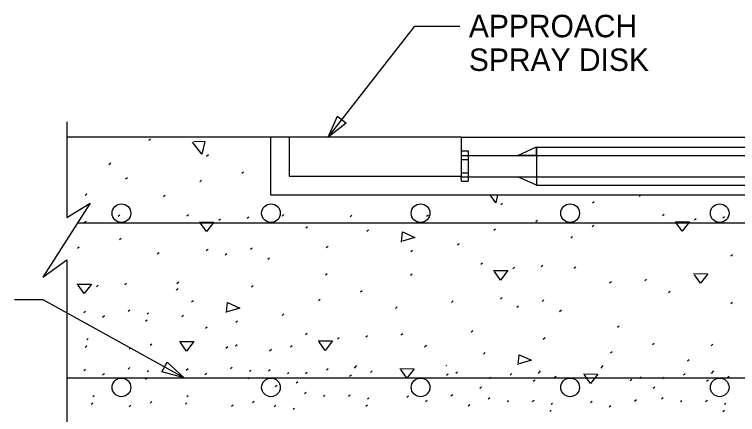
# Model space of a CAD drawing. Extents: x 3239 to 4230, y -4276 to -2494.
# Drawn here: x 3373 to 3469.7, y -3429.6 to -3376.1 of the extents above; entities that cross this region are included whole.
import ezdxf

# ---------------------------------------------------------------- set-up
doc = ezdxf.new("R2010")
doc.units = 0
doc.layers.add('2', color=7, linetype='Continuous')

msp = doc.modelspace()

# ---------------------------------------------------------------- linework, layer by layer
at = {"layer": '2'}
for p, q in [((3380.058, -3390.462), (3380.058, -3403.224)), ((3390.777, -3392.515), (3380.058, -3392.515)), ((3432.777, -3392.515), (3390.777, -3392.515)), ((3391.016, -3392.888), (3391.249, -3392.702)), ((3407.277, -3392.515), (3407.277, -3400.215)), ((3409.777, -3392.515), (3409.777, -3397.715)), ((3432.777, -3392.515), (3432.777, -3397.79)), ((3432.777, -3392.515), (3671.69, -3392.515)), ((3432.819, -3394.34), (3433.719, -3394.34)), ((3433.719, -3394.34), (3433.719, -3398.39)), ((3442.858, -3395.022), (3442.854, -3393.809)), ((3442.858, -3393.818), (3574.241, -3393.818)), ((3442.858, -3393.818), (3442.858, -3398.912)), ((3398.731, -3395.023), (3398.964, -3394.836)), ((3432.777, -3394.94), (3435.277, -3394.94)), ((3432.819, -3395.465), (3433.719, -3395.465)), ((3435.277, -3394.94), (3574.241, -3394.94)), ((3385.67, -3396.131), (3385.903, -3395.945)), ((3403.437, -3397.306), (3403.67, -3397.119)), ((3432.819, -3397.265), (3433.719, -3397.265)), ((3387.904, -3398.067), (3388.137, -3397.881)), ((3397.822, -3398.447), (3398.055, -3398.261)), ((3409.777, -3397.715), (3432.777, -3397.715)), ((3432.777, -3397.79), (3435.277, -3397.79)), ((3432.819, -3398.39), (3432.777, -3397.79)), ((3432.819, -3398.39), (3433.719, -3398.39)), ((3435.277, -3397.79), (3574.241, -3397.79)), ((3442.858, -3398.912), (3574.241, -3398.912)), ((3382.499, -3400.256), (3382.732, -3400.07)), ((3392.953, -3400.428), (3393.186, -3400.241)), ((3407.277, -3400.215), (3579.7, -3400.215)), ((3456.558, -3400.393), (3456.781, -3400.215)), ((3383.178, -3401.33), (3376.812, -3411.2)), ((3380.058, -3403.224), (3383.178, -3401.33)), ((3438.056, -3401.498), (3438.289, -3401.312)), ((3450.315, -3401.279), (3450.548, -3401.092)), ((3386.892, -3403.051), (3387.125, -3402.865)), ((3396.074, -3403.005), (3396.307, -3402.819)), ((3404.136, -3403.317), (3404.369, -3403.13)), ((3408.84, -3403.034), (3409.073, -3402.848)), ((3417.906, -3403.126), (3418.139, -3402.94)), ((3428.154, -3403.059), (3428.387, -3402.873)), ((3459.68, -3402.971), (3459.913, -3402.784)), ((3467.741, -3403.282), (3467.974, -3403.096)), ((3381.498, -3403.936), (3591.059, -3403.936)), ((3382.371, -3403.903), (3382.604, -3403.716)), ((3400.362, -3403.596), (3400.595, -3403.41)), ((3442.762, -3403.781), (3442.995, -3403.595)), ((3450.268, -3404.447), (3450.501, -3404.261)), ((3463.967, -3403.562), (3464.2, -3403.376)), ((3412.008, -3404.619), (3412.241, -3404.432)), ((3420.14, -3405.063), (3420.373, -3404.876)), ((3437.147, -3404.923), (3437.38, -3404.736)), ((3387.077, -3406.186), (3387.31, -3406)), ((3447.422, -3405.971), (3447.655, -3405.785)), ((3381.462, -3407.328), (3381.695, -3407.141)), ((3414.734, -3407.251), (3414.967, -3407.065)), ((3432.278, -3406.903), (3432.511, -3406.717)), ((3392.138, -3408.093), (3392.371, -3407.906)), ((3398.684, -3407.65), (3398.917, -3407.464)), ((3401.189, -3408.234), (3401.422, -3408.048)), ((3404.6, -3407.461), (3404.832, -3407.275)), ((3426.034, -3407.788), (3426.267, -3407.602)), ((3468.812, -3408.359), (3469.045, -3408.173)), ((3376.812, -3411.2), (3380.058, -3408.892)), ((3380.058, -3408.892), (3380.058, -3436.042)), ((3406.926, -3408.798), (3407.159, -3408.612)), ((3435.399, -3409.481), (3435.632, -3409.294)), ((3439.687, -3410.072), (3439.92, -3409.885)), ((3443.461, -3409.792), (3443.694, -3409.606)), ((3447.85, -3410.006), (3448.083, -3409.82)), ((3414.607, -3410.898), (3414.84, -3410.712)), ((3425.987, -3410.957), (3426.22, -3410.771)), ((3387.776, -3412.197), (3388.009, -3412.011)), ((3394.77, -3412.03), (3395.003, -3411.844)), ((3452.624, -3411.959), (3452.857, -3411.772)), ((3457.327, -3411.677), (3457.56, -3411.49)), ((3384.002, -3412.477), (3384.235, -3412.29)), ((3394.677, -3412.916), (3394.91, -3412.729)), ((3404.739, -3412.493), (3404.972, -3412.307)), ((3419.313, -3413.181), (3419.546, -3412.995)), ((3438.009, -3414.126), (3438.242, -3413.939)), ((3460.496, -3413.261), (3460.729, -3413.074)), ((3396.725, -3414.497), (3396.958, -3414.311)), ((3413.698, -3414.323), (3413.931, -3414.137)), ((3431.462, -3414.568), (3431.695, -3414.382)), ((3443.61, -3414.433), (3443.843, -3414.246)), ((3468.812, -3414.728), (3469.045, -3414.541)), ((3382.324, -3415.945), (3382.557, -3415.759)), ((3388.24, -3415.756), (3388.473, -3415.57)), ((3423.972, -3415.371), (3424.205, -3415.185)), ((3440.199, -3415.206), (3440.432, -3415.02)), ((3445.937, -3415.77), (3446.17, -3415.583)), ((3384.829, -3416.53), (3385.062, -3416.343)), ((3390.777, -3416.103), (3390.95, -3415.965)), ((3395.42, -3416.454), (3395.653, -3416.268)), ((3408.829, -3416.303), (3409.062, -3416.117)), ((3390.566, -3417.093), (3390.777, -3416.925)), ((3398.589, -3418.038), (3398.822, -3417.852)), ((3402.619, -3417.223), (3402.852, -3417.037)), ((3453.652, -3417.904), (3453.885, -3417.718)), ((3411.95, -3418.881), (3412.183, -3418.694)), ((3424.715, -3418.91), (3424.948, -3418.724)), ((3434.095, -3418.506), (3434.328, -3418.319)), ((3382.706, -3419.555), (3382.879, -3419.417)), ((3416.237, -3419.472), (3416.47, -3419.285)), ((3420.012, -3419.192), (3420.245, -3419.006)), ((3443.75, -3419.465), (3443.983, -3419.279)), ((3382.495, -3420.546), (3382.706, -3420.377)), ((3388.379, -3420.789), (3388.612, -3420.602)), ((3391.18, -3420.296), (3391.413, -3420.109)), ((3401.314, -3420.671), (3401.547, -3420.485)), ((3402.573, -3420.391), (3402.806, -3420.205)), ((3409.953, -3420.53), (3410.186, -3420.343)), ((3427.884, -3420.494), (3428.117, -3420.308)), ((3458.358, -3420.187), (3458.591, -3420.001)), ((3466.178, -3420.357), (3466.411, -3420.171)), ((3407.152, -3421.023), (3407.385, -3420.836)), ((3435.736, -3421.469), (3435.969, -3421.282)), ((3452.743, -3421.329), (3452.976, -3421.143)), ((3463.017, -3422.377), (3463.25, -3422.191)), ((3382.324, -3423.669), (3382.557, -3423.482)), ((3388.24, -3423.48), (3388.473, -3423.293)), ((3396.009, -3423.61), (3396.242, -3423.424)), ((3401.924, -3423.421), (3402.157, -3423.235)), ((3404.462, -3423.768), (3404.634, -3423.63)), ((3407.012, -3423.714), (3407.245, -3423.527)), ((3414.748, -3423.572), (3414.981, -3423.386)), ((3430.75, -3423.015), (3430.843, -3422.941)), ((3384.829, -3424.253), (3385.062, -3424.067)), ((3390.777, -3423.827), (3390.95, -3423.688)), ((3398.514, -3424.195), (3398.747, -3424.008)), ((3404.251, -3424.758), (3404.462, -3424.59)), ((3409.55, -3424.061), (3409.722, -3423.922)), ((3411.948, -3424.065), (3412.181, -3423.879)), ((3417.855, -3424.416), (3418.088, -3424.23)), ((3420.655, -3423.923), (3420.888, -3423.737)), ((3430.79, -3424.299), (3431.023, -3424.112)), ((3432.048, -3424.019), (3432.281, -3423.833)), ((3436.51, -3424.767), (3436.743, -3424.581)), ((3439.311, -3424.274), (3439.544, -3424.088)), ((3445.218, -3424.625), (3445.451, -3424.439)), ((3456.611, -3424.721), (3456.843, -3424.535)), ((3459.685, -3424.767), (3459.918, -3424.581)), ((3462.485, -3424.274), (3462.718, -3424.088)), ((3468.392, -3424.625), (3468.625, -3424.439)), ((3380.058, -3424.646), (3612.142, -3424.646)), ((3390.566, -3424.817), (3390.777, -3424.648)), ((3410.713, -3425.328), (3410.946, -3425.141)), ((3442.417, -3425.118), (3442.65, -3424.932)), ((3455.352, -3425.001), (3455.585, -3424.815)), ((3465.591, -3425.118), (3465.824, -3424.932)), ((3407.913, -3425.821), (3408.145, -3425.634)), ((3411.808, -3426.756), (3412.041, -3426.57)), ((3435.276, -3426.03), (3435.509, -3425.843)), ((3458.45, -3426.03), (3458.683, -3425.843)), ((3383.525, -3427.162), (3383.698, -3427.024)), ((3396.099, -3427.162), (3396.271, -3427.024)), ((3414.345, -3427.103), (3414.518, -3426.965)), ((3417.715, -3427.107), (3417.948, -3426.921)), ((3420.252, -3427.454), (3420.425, -3427.316)), ((3425.485, -3427.238), (3425.718, -3427.052)), ((3431.4, -3427.049), (3431.633, -3426.863)), ((3436.371, -3427.459), (3436.604, -3427.272)), ((3459.545, -3427.459), (3459.778, -3427.272)), ((3383.314, -3428.152), (3383.525, -3427.983)), ((3388.379, -3428.512), (3388.612, -3428.326)), ((3391.18, -3428.019), (3391.413, -3427.833)), ((3395.888, -3428.152), (3396.099, -3427.983)), ((3402.064, -3428.454), (3402.297, -3428.267)), ((3404.865, -3427.961), (3405.098, -3427.774)), ((3407.773, -3428.512), (3408.006, -3428.325)), ((3420.041, -3428.445), (3420.252, -3428.276)), ((3427.989, -3427.822), (3428.222, -3427.636)), ((3433.726, -3428.386), (3433.937, -3428.217)), ((3438.908, -3427.805), (3439.081, -3427.667)), ((3442.277, -3427.81), (3442.51, -3427.623)), ((3444.815, -3428.156), (3444.987, -3428.018)), ((3450.047, -3427.94), (3450.28, -3427.754)), ((3452.551, -3428.524), (3452.784, -3428.338)), ((3455.962, -3427.751), (3456.195, -3427.565)), ((3462.082, -3427.805), (3462.255, -3427.667)), ((3465.452, -3427.81), (3465.685, -3427.623)), ((3467.989, -3428.156), (3468.162, -3428.018)), ((3410.31, -3428.859), (3410.483, -3428.72)), ((3444.604, -3429.147), (3444.815, -3428.978)), ((3467.778, -3429.147), (3467.989, -3428.978))]:
    msp.add_line(p, q, dxfattribs=at)
for points in [[(3414.964, -3392.515), (3426.588, -3377.65), (3432.581, -3377.65)], [(3397.003, -3393.011), (3398.471, -3393.081), (3398.074, -3394.782), (3396.863, -3393.151)], [(3437.642, -3400.215), (3437.399, -3401.257), (3436.625, -3400.215)], [(3397.759, -3403.829), (3399.693, -3403.852), (3398.714, -3405.111), (3397.899, -3403.969)], [(3461.364, -3403.795), (3463.298, -3403.818), (3462.319, -3405.076), (3461.504, -3403.935)], [(3424.799, -3406.507), (3424.939, -3405.156), (3426.57, -3405.901), (3424.916, -3406.391)], [(3437.084, -3410.305), (3439.017, -3410.328), (3438.039, -3411.586), (3437.223, -3410.444)], [(3463.818, -3410.73), (3465.752, -3410.753), (3464.773, -3412.012), (3463.958, -3410.87)], [(3381.399, -3412.124), (3383.333, -3412.148), (3382.354, -3413.406), (3381.539, -3412.264)], [(3395.716, -3424.646), (3376.867, -3414.226), (3373.037, -3414.226)], [(3401.384, -3415.942), (3401.524, -3414.59), (3403.155, -3415.336), (3401.501, -3415.825)], [(3395.084, -3419.789), (3397.017, -3419.813), (3396.039, -3421.071), (3395.224, -3419.929)], [(3413.634, -3419.705), (3415.568, -3419.728), (3414.59, -3420.986), (3413.774, -3419.844)], [(3440.395, -3422.913), (3440.535, -3421.562), (3442.166, -3422.307), (3440.512, -3422.797)], [(3418.784, -3423.015), (3418.48, -3423.377)], [(3424.559, -3423.417), (3426.493, -3423.44), (3425.514, -3424.698), (3424.699, -3423.557)], [(3451.728, -3423.015), (3451.424, -3423.377)], [(3443.347, -3423.717), (3443.043, -3424.08)], [(3449.122, -3424.119), (3451.055, -3424.142), (3450.077, -3425.4), (3449.261, -3424.259)], [(3466.521, -3423.717), (3466.217, -3424.08)]]:
    msp.add_lwpolyline(points, dxfattribs=at)
for points in [[(3417.402, -3390.614), (3414.964, -3392.515), (3416.221, -3389.69)], [(3442.854, -3393.809), (3442.858, -3394.94), (3440.366, -3394.94)], [(3440.354, -3397.79), (3442.855, -3397.797), (3442.858, -3398.912)], [(3393.454, -3422.538), (3395.716, -3424.646), (3392.728, -3423.851)]]:
    msp.add_lwpolyline(points, close=True, dxfattribs=at)
for centre in [(3387.337, -3402.653), (3407.337, -3402.653), (3427.337, -3402.653), (3447.337, -3402.653), (3467.337, -3402.653), (3387.337, -3425.929), (3407.337, -3425.929), (3427.337, -3425.929), (3447.337, -3425.929), (3467.337, -3425.929)]:
    msp.add_circle(centre, 1.247, dxfattribs=at)

# ---------------------------------------------------------------- texts
for s, p in [('APPROACH', (3433.797, -3379.15)), ('SPRAY DISK', (3433.797, -3383.65))]:
    msp.add_text(s, height=3, dxfattribs=at).set_placement(p)

doc.saveas('drawing.dxf')
